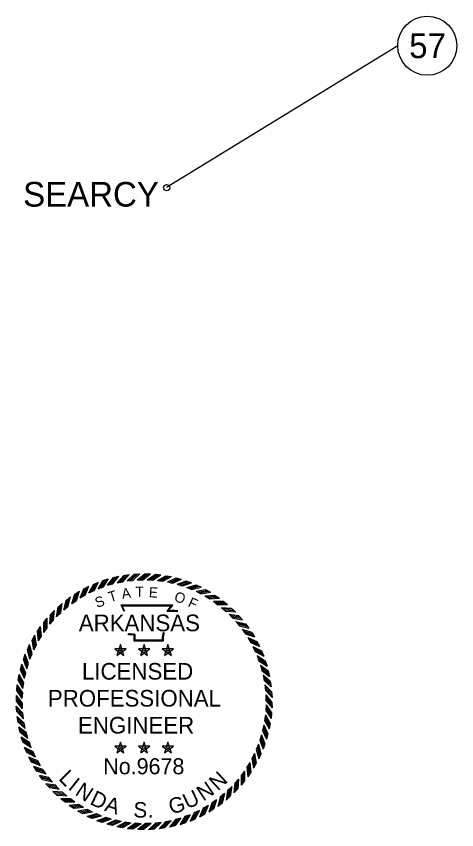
# Model space of a CAD drawing. Extents: x -13171 to 18763, y -8840 to 11152.
# Drawn here: x 13229 to 17512, y -8799 to -895 of the extents above; entities that cross this region are included whole.
import ezdxf

# ---------------------------------------------------------------- set-up
doc = ezdxf.new("R2010")
doc.units = 0
for name, color, linetype in [('Level 2', 7, 'Continuous'), ('Level 48', 7, 'Continuous'), ('Level 52', 7, 'Continuous')]:
    doc.layers.add(name, color=color, linetype=linetype)

msp = doc.modelspace()

# ---------------------------------------------------------------- linework, layer by layer
at = {"layer": 'Level 48'}
msp.add_line((16938.6, -1181.5), (14690.6, -2559.2), dxfattribs=at)
for centre, radius in [((17225.5, -1181.5), 286.9), ((14690.6, -2559.2), 30.2)]:
    msp.add_circle(centre, radius, dxfattribs=at)
at = {"layer": 'Level 52'}
for p, q in [((14274.6, -6328.5), (14328.3, -6319)), ((14376.6, -6316.3), (14430.9, -6311.3)), ((14479.8, -6313.2), (14534.3, -6313.2)), ((14581.9, -6317.3), (14636.2, -6321.3)), ((13979.6, -6414.7), (14029.2, -6392.3)), ((14075.4, -6377.8), (14126.8, -6359.7)), ((14174, -6349), (14226.7, -6335.2)), ((14211.5, -6398.5), (14265.3, -6389)), ((14307.9, -6380.8), (14362.3, -6375.8)), ((14405.4, -6371.2), (14460.1, -6371.2)), ((14503.4, -6369.7), (14557.9, -6373.7)), ((14601.2, -6376.3), (14655.2, -6384.8)), ((14683.7, -6330.6), (14737.5, -6339)), ((14698.2, -6390.9), (14751.2, -6403.8)), ((14784.1, -6352.1), (14837.1, -6365)), ((14882.4, -6382), (14934.1, -6399.2)), ((13798.6, -6511.4), (13843.9, -6481.2)), ((13887.1, -6459.3), (13934.7, -6432.9)), ((13935.5, -6498.1), (13985.3, -6475.7)), ((14024.7, -6457.3), (14076.1, -6439.1)), ((14116.8, -6424), (14169.7, -6410.1)), ((14793.5, -6413.5), (14845.4, -6430.7)), ((14886.7, -6443.8), (14936.9, -6465.3)), ((14977.9, -6419.8), (15028, -6441.2)), ((15069.9, -6465.4), (15118.1, -6490.8)), ((13714.7, -6570.7), (13757.3, -6536.8)), ((13850.1, -6546), (13897.8, -6519.6)), ((14977.1, -6481.8), (15025.4, -6507.4)), ((15064, -6527.1), (15110, -6556.6)), ((15157.9, -6518.4), (15203.8, -6547.8)), ((13636, -6636.7), (13675.7, -6599.4)), ((13692.4, -6662.3), (13735.2, -6628.4)), ((13768.8, -6600.9), (13814.3, -6570.6)), ((15146.9, -6579.4), (15190.3, -6612.6)), ((15225.2, -6638.4), (15265.7, -6675)), ((15241.2, -6578.5), (15284.5, -6611.6)), ((13563, -6708.9), (13599.5, -6668.5)), ((13621.4, -6729.8), (13661.2, -6692.5)), ((15298.3, -6703.7), (15335.7, -6743.5)), ((15319.2, -6645.3), (15359.6, -6681.8)), ((15391.5, -6718.3), (15428.7, -6758)), ((13496.2, -6787), (13529.2, -6743.7)), ((13556.1, -6803), (13592.7, -6762.4)), ((15365.8, -6774.7), (15399.7, -6817.5)), ((15457.4, -6797), (15491.3, -6839.7)), ((13436.1, -6870.2), (13465.5, -6824.4)), ((13497.1, -6881.2), (13530.3, -6837.8)), ((15427.2, -6851.1), (15457.5, -6896.6)), ((13383, -6958.2), (13408.5, -6910)), ((13444.8, -6964.1), (13474.3, -6918.1)), ((15482.1, -6932.4), (15508.5, -6980.1)), ((15516.7, -6880.9), (15546.9, -6926.2)), ((13337.5, -7050.2), (13358.9, -7000.1)), ((13399.5, -7051), (13425.1, -7002.8)), ((14241.7, -7000.7), (14207.6, -7105.3)), ((14275.7, -7105.2), (14241.8, -7000.6)), ((14472.8, -7000.7), (14438.7, -7105.3)), ((14506.8, -7105.2), (14472.9, -7000.6)), ((14703.9, -7000.7), (14669.8, -7105.3)), ((14737.9, -7105.2), (14704, -7000.6)), ((15530.1, -7017.8), (15552.5, -7067.6)), ((15568.8, -6969.4), (15595.2, -7017)), ((13299.6, -7145.7), (13316.9, -7094)), ((13361.5, -7141.4), (13383, -7091.2)), ((14296.6, -7040.6), (14186.7, -7040.5)), ((14186.7, -7040.6), (14275.7, -7105.4)), ((14207.7, -7105.2), (14296.8, -7040.7)), ((14233.9, -7058.2), (14250.2, -7058.2)), ((14241.8, -7052.3), (14241.8, -7066.1)), ((14527.8, -7040.6), (14417.8, -7040.5)), ((14417.9, -7040.6), (14506.8, -7105.4)), ((14438.8, -7105.2), (14527.9, -7040.7)), ((14465, -7058.2), (14481.3, -7058.2)), ((14472.9, -7052.3), (14472.9, -7066.1)), ((14758.9, -7040.6), (14648.9, -7040.5)), ((14649, -7040.6), (14737.9, -7105.4)), ((14670, -7105.2), (14759, -7040.7)), ((14696.1, -7058.2), (14712.4, -7058.2)), ((14704, -7052.3), (14704, -7066.1)), ((15570.9, -7107), (15589.1, -7158.4)), ((15613.5, -7061.9), (15635.8, -7111.5)), ((13269.8, -7244), (13282.7, -7191.1)), ((13331.2, -7234.6), (13348.4, -7182.8)), ((15650.3, -7157.7), (15668.5, -7209.1)), ((15604.1, -7199.2), (15618, -7252)), ((15679.1, -7256.3), (15693, -7309)), ((13248.2, -7344.4), (13256.7, -7290.6)), ((13308.6, -7330), (13321.5, -7276.9)), ((15629.7, -7293.8), (15639.1, -7347.6)), ((13235, -7446.3), (13239, -7391.9)), ((13294, -7426.9), (13302.5, -7372.9)), ((15647.3, -7390.2), (15652.3, -7444.6)), ((15699.7, -7356.9), (15709.1, -7410.6)), ((13230.3, -7548.9), (13229.8, -7494.4)), ((13287.4, -7524.7), (13291.4, -7470.2)), ((15656.9, -7487.7), (15657.4, -7542.4)), ((15711.9, -7458.9), (15716.9, -7513.2)), ((13288.9, -7622.7), (13288.4, -7568.1)), ((15658.4, -7585.7), (15654.4, -7640.2)), ((15715.6, -7561.6), (15716.1, -7616)), ((13234, -7651.5), (13229, -7597.3)), ((13298.5, -7720.2), (13293.5, -7665.9)), ((15710.8, -7664.2), (15706.8, -7718.5)), ((13246.2, -7753.5), (13236.7, -7699.8)), ((15651.9, -7683.5), (15643.4, -7737.5)), ((13266.7, -7854.1), (13252.9, -7801.4)), ((13316.2, -7816.7), (13306.7, -7762.9)), ((15637.2, -7780.5), (15624.3, -7833.5)), ((15697.6, -7766), (15689.1, -7819.8)), ((13295.5, -7952.7), (13277.4, -7901.3)), ((13341.7, -7911.3), (13327.8, -7858.5)), ((15614.7, -7875.8), (15597.4, -7927.7)), ((15676, -7866.4), (15663.1, -7919.4)), ((13375, -8003.5), (13356.8, -7952)), ((14241.7, -7948.3), (14207.6, -8052.9)), ((14275.7, -8052.8), (14241.8, -7948.2)), ((14472.8, -7948.3), (14438.7, -8052.9)), ((14506.8, -8052.8), (14472.9, -7948.2)), ((14703.9, -7948.3), (14669.8, -8052.9)), ((14737.9, -8052.8), (14704, -7948.2)), ((15584.3, -7969), (15562.8, -8019.2)), ((15646.2, -7964.7), (15629, -8016.4)), ((13332.4, -8048.6), (13310, -7998.9)), ((13415.7, -8092.6), (13393.3, -8042.8)), ((14296.6, -7988.2), (14186.7, -7988.1)), ((14186.7, -7988.2), (14275.7, -8053)), ((14207.7, -8052.8), (14296.8, -7988.3)), ((14233.9, -8005.8), (14250.2, -8005.8)), ((14241.8, -7999.9), (14241.8, -8013.7)), ((14527.8, -7988.2), (14417.8, -7988.1)), ((14417.9, -7988.2), (14506.8, -8053)), ((14438.8, -8052.8), (14527.9, -7988.3)), ((14465, -8005.8), (14481.3, -8005.8)), ((14472.9, -7999.9), (14472.9, -8013.7)), ((14758.9, -7988.2), (14648.9, -7988.1)), ((14649, -7988.2), (14737.9, -8053)), ((14670, -8052.8), (14759, -7988.3)), ((14696.1, -8005.8), (14712.4, -8005.8)), ((14704, -7999.9), (14704, -8013.7)), ((15546.3, -8059.4), (15520.8, -8107.7)), ((15608.4, -8060.2), (15586.9, -8110.3)), ((13377, -8141.1), (13350.6, -8093.4)), ((13463.7, -8178.1), (13437.3, -8130.3)), ((13429.1, -8229.6), (13398.9, -8184.2)), ((13518.6, -8259.3), (13488.3, -8213.9)), ((15501, -8146.3), (15471.6, -8192.3)), ((15562.8, -8152.2), (15537.3, -8200.4)), ((13488.4, -8313.5), (13454.5, -8270.8)), ((13580, -8335.7), (13546.1, -8292.9)), ((15448.7, -8229.2), (15415.6, -8272.6)), ((15509.8, -8240.2), (15480.4, -8286.1)), ((13554.4, -8392.2), (13517.1, -8352.4)), ((13647.5, -8406.8), (13610.2, -8366.9)), ((15389.7, -8307.5), (15353.1, -8348)), ((15449.7, -8323.5), (15416.6, -8366.8)), ((13626.6, -8465.2), (13586.2, -8428.6)), ((13720.7, -8472), (13680.1, -8435.4)), ((15253.4, -8448.1), (15210.6, -8482.1)), ((15324.5, -8380.6), (15284.6, -8418)), ((15382.9, -8401.5), (15346.3, -8441.9)), ((13704.7, -8532), (13661.4, -8498.9)), ((13798.9, -8531), (13755.5, -8497.9)), ((15177, -8509.5), (15131.5, -8539.8)), ((15309.9, -8473.8), (15270.1, -8511)), ((13787.9, -8592.1), (13742.1, -8562.7)), ((13881.8, -8583.3), (13835.8, -8553.9)), ((13968.7, -8628.6), (13920.5, -8603.1)), ((15010.3, -8612.4), (14960.5, -8634.8)), ((15095.8, -8564.4), (15048, -8590.8)), ((15147.3, -8599), (15101.9, -8629.2)), ((15231.2, -8539.7), (15188.5, -8573.6)), ((13875.9, -8645.1), (13827.7, -8619.6)), ((13967.9, -8690.7), (13917.8, -8669.2)), ((14059.1, -8666.6), (14008.9, -8645.1)), ((14152.3, -8697), (14100.5, -8679.7)), ((14829, -8686.4), (14776.2, -8700.3)), ((14921.2, -8653.2), (14869.7, -8671.4)), ((15058.8, -8651.1), (15011.1, -8677.5)), ((14063.4, -8728.5), (14011.7, -8711.3)), ((14161.7, -8758.3), (14108.8, -8745.4)), ((14247.7, -8719.6), (14194.6, -8706.6)), ((14262.1, -8779.9), (14208.3, -8771.4)), ((14344.6, -8734.2), (14290.6, -8725.7)), ((14442.4, -8740.7), (14387.9, -8736.7)), ((14540.4, -8739.2), (14485.8, -8739.7)), ((14637.9, -8729.6), (14583.6, -8734.6)), ((14734.3, -8712), (14680.6, -8721.4)), ((14771.8, -8761.4), (14719.1, -8775.3)), ((14870.4, -8732.6), (14819, -8750.8)), ((14966.3, -8695.8), (14916.6, -8718.1)), ((14364, -8793.1), (14309.6, -8789.1)), ((14466.6, -8797.9), (14412.1, -8798.4)), ((14569.2, -8794.2), (14515, -8799.2)), ((14671.2, -8782), (14617.5, -8791.4))]:
    msp.add_line(p, q, dxfattribs=at)
for points in [[(14247.3, -6392), (14310.4, -6321.9)], [(14265.2, -6389), (14328.3, -6319)], [(14307.8, -6380.9), (14376.5, -6316.3)], [(14325.3, -6379.4), (14394, -6314.9)], [(14344.1, -6377.3), (14412.8, -6312.7)], [(14362.2, -6375.8), (14430.9, -6311.2)], [(14405.4, -6371.3), (14479.7, -6313.3)], [(14422.9, -6371.4), (14497.3, -6313.5)], [(14441.8, -6371), (14516.2, -6313)], [(14460, -6371.2), (14534.3, -6313.2)], [(14503.4, -6369.7), (14581.8, -6317.4)], [(14520.9, -6371.2), (14599.2, -6318.8)], [(14539.8, -6372.2), (14618.2, -6319.8)], [(14557.8, -6373.7), (14636.2, -6321.3)], [(13968.6, -6482.9), (14012.7, -6399.6)], [(13985.3, -6475.6), (14029.3, -6392.3)], [(14024.6, -6457.4), (14075.4, -6377.9)], [(14041.2, -6451.7), (14092, -6372.2)], [(14058.9, -6445), (14109.7, -6365.5)], [(14076.1, -6439.1), (14126.8, -6359.6)], [(14116.8, -6424.1), (14173.9, -6349.1)], [(14133.8, -6419.8), (14190.9, -6344.8)], [(14152, -6414.6), (14209.1, -6339.6)], [(14169.6, -6410.1), (14226.7, -6335.1)], [(14211.4, -6398.5), (14274.6, -6328.5)], [(14228.7, -6395.7), (14291.9, -6325.6)], [(14601.2, -6376.3), (14683.6, -6330.6)], [(14618.5, -6379.2), (14700.9, -6333.5)], [(14637.2, -6381.7), (14719.7, -6336)], [(14655.1, -6384.7), (14737.6, -6339)], [(14698.1, -6390.9), (14784, -6352.2)], [(14715.1, -6395.2), (14801, -6356.5)], [(14733.6, -6399.3), (14819.5, -6360.5)], [(14751.2, -6403.8), (14837.1, -6365)], [(14793.5, -6413.5), (14882.3, -6382)], [(14810, -6419.2), (14898.9, -6387.7)], [(14828.1, -6424.8), (14917, -6393.3)], [(14845.3, -6430.7), (14934.2, -6399.1)], [(13814.2, -6570.6), (13843.9, -6481.2)], [(13850, -6546.1), (13887, -6459.4)], [(13865.4, -6537.8), (13902.4, -6451.1)], [(13881.8, -6528.2), (13918.8, -6441.5)], [(13897.8, -6519.6), (13934.8, -6432.9)], [(13935.5, -6498.1), (13979.5, -6414.8)], [(13951.5, -6491.1), (13995.6, -6407.7)], [(14886.6, -6443.9), (14977.8, -6419.8)], [(14902.7, -6450.9), (14993.9, -6426.8)], [(14920.3, -6458), (15011.4, -6433.9)], [(14936.9, -6465.3), (15028, -6441.2)], [(14977, -6481.8), (15069.8, -6465.4)], [(14992.4, -6490.2), (15085.3, -6473.7)], [(13706.3, -6651.6), (13728.5, -6560)], [(13720.8, -6639.5), (13743, -6547.9)], [(13735.2, -6628.4), (13757.4, -6536.8)], [(13768.8, -6601), (13798.5, -6511.5)], [(13783.5, -6591.4), (13813.2, -6501.9)], [(13799, -6580.6), (13828.7, -6491.1)], [(15009.4, -6498.7), (15102.2, -6482.2)], [(15025.3, -6507.3), (15118.1, -6490.8)], [(15063.9, -6527.1), (15157.8, -6518.4)], [(15078.6, -6536.7), (15172.5, -6528)], [(15094.8, -6546.6), (15188.6, -6537.8)], [(15110, -6556.5), (15203.8, -6547.7)], [(13621.4, -6729.9), (13635.9, -6636.8)], [(13634.3, -6718), (13648.8, -6624.9)], [(13647.8, -6704.8), (13662.4, -6611.6)], [(13661.1, -6692.5), (13675.7, -6599.3)], [(13692.4, -6662.4), (13714.6, -6570.8)], [(14276.8, -6677.9), (14247.8, -6615), (14750.3, -6614.7), (14708.3, -6667.5), (14742.4, -6667), (14770.9, -6666.7), (14799.4, -6669.8)], [(14284, -6674.6), (14260.2, -6623), (14733.7, -6622.7), (14691.6, -6675.6), (14742.5, -6675), (14770.6, -6674.6), (14798.6, -6677.7)], [(15146.8, -6579.4), (15241.1, -6578.5)], [(15160.6, -6590.2), (15254.9, -6589.2)], [(15175.9, -6601.4), (15270.2, -6600.4)], [(15190.3, -6612.5), (15284.5, -6611.6)], [(15225.1, -6638.4), (15319.1, -6645.2)], [(13556.1, -6803), (13562.9, -6709)], [(13568, -6790.1), (13574.8, -6696.1)], [(13580.4, -6775.8), (13587.2, -6681.8)], [(13592.7, -6762.5), (13599.5, -6668.4)], [(15238, -6650.3), (15332, -6657.1)], [(15252.3, -6662.7), (15346.3, -6669.5)], [(15265.7, -6675), (15359.7, -6681.8)], [(15298.2, -6703.7), (15391.4, -6718.2)], [(15310.1, -6716.6), (15403.2, -6731.1)], [(13497.1, -6881.3), (13496.2, -6787.1)], [(13507.9, -6867.5), (13506.9, -6773.2)], [(13519.1, -6852.2), (13518.1, -6757.9)], [(13530.2, -6837.9), (13529.2, -6743.6)], [(15323.4, -6730.1), (15416.5, -6744.7)], [(15335.7, -6743.4), (15428.8, -6758)], [(15365.7, -6774.7), (15457.4, -6796.9)], [(15376.5, -6788.6), (15468.1, -6810.8)], [(13444.8, -6964.2), (13436.1, -6870.3)], [(13454.4, -6949.5), (13445.7, -6855.7)], [(13464.3, -6933.4), (13455.5, -6839.5)], [(13474.2, -6918.2), (13465.4, -6824.3)], [(15388.6, -6803.1), (15480.2, -6825.3)], [(15399.7, -6817.5), (15491.4, -6839.7)], [(15427.1, -6851.1), (15516.6, -6880.8)], [(15436.7, -6865.8), (15526.2, -6895.5)], [(13407.9, -7035.7), (13391.4, -6942.9)], [(13416.4, -7018.8), (13399.9, -6925.9)], [(13425, -7002.8), (13408.5, -6910)], [(14671.1, -6888.5), (14662.5, -6895.5), (14659.7, -6905.9), (14656.8, -6931.9), (14656.8, -6966.7), (14376.3, -6966.7), (14376.3, -6919.8), (14376.3, -6909.4), (14364.9, -6905.9), (14325, -6905.9), (14317.9, -6895.1)], [(14666, -6882.3), (14655.5, -6890.9), (14651.8, -6904.4), (14648.9, -6931.5), (14648.9, -6958.7), (14384.3, -6958.7), (14384.3, -6919.8), (14384.3, -6903.5), (14366.1, -6897.9), (14329.3, -6897.9), (14324.6, -6890.7)], [(15447.6, -6881.3), (15537, -6911)], [(15457.5, -6896.5), (15547, -6926.2)], [(15482, -6932.3), (15568.7, -6969.3)], [(15490.4, -6947.7), (15577.1, -6984.7)], [(13368.6, -7125.4), (13344.5, -7034.3)], [(13375.7, -7107.9), (13351.6, -7016.7)], [(13383, -7091.2), (13358.9, -7000.1)], [(13399.5, -7051.1), (13383.1, -6958.3)], [(15499.9, -6964.1), (15586.6, -7001.1)], [(15508.5, -6980.1), (15595.2, -7017.1)], [(15530, -7017.8), (15613.4, -7061.8)], [(15537.1, -7033.8), (15620.4, -7077.9)], [(13342.5, -7200), (13310.9, -7111.1)], [(13348.4, -7182.8), (13316.8, -7094)], [(13361.6, -7141.5), (13337.5, -7050.3)], [(15545.2, -7050.9), (15628.6, -7095)], [(15552.5, -7067.6), (15635.9, -7111.6)], [(15570.8, -7106.9), (15650.2, -7157.7)], [(13321.4, -7277), (13282.7, -7191)], [(13331.2, -7234.7), (13299.7, -7145.8)], [(13336.9, -7218.1), (13305.4, -7129.2)], [(15576.5, -7123.5), (15655.9, -7174.3)], [(15583.2, -7141.2), (15662.6, -7192)], [(15589.1, -7158.4), (15668.5, -7209.1)], [(13308.6, -7330.1), (13269.9, -7244.1)], [(13312.9, -7313.1), (13274.2, -7227.1)], [(13317, -7294.6), (13278.2, -7208.6)], [(15604.1, -7199.1), (15679, -7256.2)], [(15608.4, -7216.1), (15683.3, -7273.3)], [(15613.6, -7234.3), (15688.6, -7291.4)], [(15618, -7251.9), (15693, -7309)], [(13294, -7427), (13248.3, -7344.5)], [(13296.9, -7409.7), (13251.2, -7327.2)], [(13299.4, -7390.9), (13253.7, -7308.5)], [(13302.4, -7373), (13256.7, -7290.6)], [(15629.6, -7293.7), (15699.6, -7356.9)], [(15632.5, -7311), (15702.5, -7374.2)], [(15636.2, -7329.6), (15706.2, -7392.7)], [(15639.2, -7347.5), (15709.2, -7410.6)], [(13288.9, -7507.3), (13236.5, -7428.9)], [(13289.9, -7488.4), (13237.5, -7410)], [(13291.4, -7470.3), (13239, -7391.9)], [(15647.2, -7390.1), (15711.8, -7458.8)], [(15648.7, -7407.6), (15713.2, -7476.3)], [(15650.8, -7426.4), (15715.4, -7495.1)], [(13288.4, -7568.2), (13229.7, -7494.3)], [(13287.4, -7524.8), (13235.1, -7446.4)], [(15652.3, -7444.5), (15716.9, -7513.2)], [(15656.9, -7487.7), (15715.5, -7561.5)], [(15656.9, -7505.2), (15715.5, -7579)], [(13288.4, -7586.3), (13229.7, -7512.5)], [(13289, -7605.2), (13230.3, -7531.4)], [(13289, -7622.8), (13230.3, -7549)], [(15657.5, -7524.1), (15716.1, -7597.9)], [(15657.5, -7542.3), (15716.1, -7616.1)], [(15658.4, -7585.7), (15710.8, -7664.1)], [(13293.5, -7665.9), (13228.9, -7597.2)], [(13295, -7684), (13230.4, -7615.3)], [(13297.1, -7702.8), (13232.6, -7634.1)], [(13298.6, -7720.3), (13234, -7651.6)], [(15654.5, -7640.2), (15706.8, -7718.5)], [(15656, -7622.1), (15708.3, -7700.5)], [(15656.9, -7603.2), (15709.3, -7681.6)], [(13306.7, -7762.9), (13236.7, -7699.8)], [(13309.6, -7780.8), (13239.6, -7717.7)], [(13313.3, -7799.4), (13243.3, -7736.3)], [(15643.4, -7737.4), (15689.1, -7819.9)], [(15646.4, -7719.5), (15692.1, -7802)], [(15648.9, -7700.8), (15694.7, -7783.2)], [(15651.8, -7683.5), (15697.5, -7765.9)], [(13316.2, -7816.7), (13246.2, -7753.6)], [(13327.8, -7858.5), (13252.8, -7801.4)], [(13332.3, -7876.1), (13257.3, -7819)], [(15628.8, -7815.9), (15667.6, -7901.8)], [(15632.9, -7797.4), (15671.7, -7883.3)], [(15637.2, -7780.4), (15676, -7866.3)], [(13337.5, -7894.3), (13262.5, -7837.2)], [(13341.8, -7911.3), (13266.8, -7854.2)], [(13356.8, -7952.1), (13277.3, -7901.3)], [(15608.9, -7892.4), (15640.5, -7981.2)], [(15614.6, -7875.8), (15646.2, -7964.6)], [(15624.4, -7833.5), (15663.1, -7919.4)], [(13362.6, -7969.2), (13283.2, -7918.5)], [(13369.4, -7986.9), (13289.9, -7936.2)], [(13375, -8003.5), (13295.6, -7952.8)], [(15584.3, -7969), (15608.3, -8060.1)], [(15597.5, -7927.6), (15629, -8016.5)], [(15603.4, -7910.4), (15634.9, -7999.3)], [(13393.3, -8042.9), (13310, -7998.9)], [(13400.6, -8059.5), (13317.3, -8015.5)], [(13408.8, -8076.6), (13325.4, -8032.6)], [(13415.8, -8092.7), (13332.5, -8048.6)], [(15546.3, -8059.3), (15562.8, -8152.1)], [(15562.9, -8019.2), (15587, -8110.4)], [(15570.2, -8002.6), (15594.2, -8093.7)], [(15577.2, -7985), (15601.3, -8076.2)], [(13437.3, -8130.4), (13350.6, -8093.4)], [(13445.9, -8146.3), (13359.2, -8109.3)], [(13455.5, -8162.7), (13368.7, -8125.7)], [(13463.8, -8178.1), (13377.1, -8141.1)], [(15520.8, -8107.6), (15537.3, -8200.5)], [(15529.5, -8091.7), (15545.9, -8184.5)], [(15538, -8074.7), (15554.4, -8167.6)], [(13488.3, -8213.9), (13398.9, -8184.2)], [(13498.3, -8229.1), (13408.8, -8199.4)], [(13509.1, -8244.6), (13419.6, -8214.9)], [(15471.6, -8192.3), (15480.4, -8286.1)], [(15481.6, -8177.1), (15490.3, -8271)], [(15491.4, -8160.9), (15500.2, -8254.8)], [(15501, -8146.2), (15509.8, -8240.1)], [(13518.7, -8259.3), (13429.2, -8229.6)], [(13546.1, -8293), (13454.5, -8270.8)], [(13557.2, -8307.3), (13465.6, -8285.1)], [(13569.3, -8321.9), (13477.7, -8299.7)], [(15415.6, -8272.6), (15416.6, -8366.8)], [(15426.8, -8258.3), (15427.7, -8352.5)], [(15437.9, -8243), (15438.9, -8337.2)], [(15448.7, -8229.1), (15449.7, -8323.4)], [(13580.1, -8335.7), (13488.5, -8313.5)], [(13610.2, -8367), (13517, -8352.4)], [(13622.5, -8380.4), (13529.3, -8365.8)], [(15353.2, -8348), (15346.3, -8442)], [(15365.5, -8334.6), (15358.6, -8428.6)], [(15377.8, -8320.3), (15371, -8414.3)], [(15389.7, -8307.4), (15382.9, -8401.4)], [(13635.7, -8393.9), (13542.6, -8379.3)], [(13647.6, -8406.8), (13554.5, -8392.2)], [(13680.2, -8435.5), (13586.1, -8428.6)], [(13693.5, -8447.8), (13599.5, -8440.9)], [(13707.8, -8460.1), (13613.8, -8453.3)], [(15253.4, -8448), (15231.2, -8539.7)], [(15284.7, -8418), (15270.1, -8511.1)], [(15298, -8405.7), (15283.5, -8498.8)], [(15311.6, -8392.4), (15297, -8485.6)], [(15324.5, -8380.5), (15309.9, -8473.7)], [(13720.7, -8472), (13626.7, -8465.2)], [(13755.6, -8497.9), (13661.3, -8498.9)], [(13769.9, -8509.1), (13675.6, -8510)], [(13785.2, -8520.2), (13690.9, -8521.2)], [(13799, -8531), (13704.7, -8532)], [(15146.8, -8529.9), (15117.1, -8619.4)], [(15162.3, -8519), (15132.6, -8608.5)], [(15177, -8509.4), (15147.3, -8598.9)], [(15210.7, -8482), (15188.5, -8573.7)], [(15225, -8470.9), (15202.8, -8562.5)], [(15239.6, -8458.8), (15217.4, -8550.4)], [(13835.9, -8553.9), (13742, -8562.7)], [(13851.1, -8563.9), (13757.2, -8572.6)], [(13867.2, -8573.7), (13773.3, -8582.5)], [(13881.9, -8583.3), (13788, -8592.1)], [(13920.5, -8603.1), (13827.7, -8619.6)], [(13936.5, -8611.8), (13843.6, -8628.2)], [(15010.4, -8612.3), (14966.3, -8695.7)], [(15048.1, -8590.8), (15011.1, -8677.6)], [(15064, -8582.2), (15027, -8668.9)], [(15080.4, -8572.7), (15043.4, -8659.4)], [(15095.8, -8564.3), (15058.8, -8651)], [(15131.6, -8539.8), (15101.9, -8629.3)], [(13953.4, -8620.3), (13860.6, -8636.7)], [(13968.8, -8628.6), (13876, -8645.1)], [(14008.9, -8645.2), (13917.8, -8669.3)], [(14025.6, -8652.5), (13934.4, -8676.5)], [(14043.1, -8659.5), (13952, -8683.6)], [(14059.2, -8666.6), (13968, -8690.7)], [(14100.5, -8679.8), (14011.7, -8711.3)], [(14117.7, -8685.7), (14028.8, -8717.2)], [(14135.8, -8691.3), (14046.9, -8722.8)], [(14812, -8690.7), (14754.9, -8765.6)], [(14829, -8686.4), (14771.9, -8761.3)], [(14869.8, -8671.4), (14819, -8750.8)], [(14886.9, -8665.5), (14836.2, -8744.9)], [(14904.6, -8658.8), (14853.9, -8738.2)], [(14921.2, -8653.1), (14870.5, -8732.5)], [(14960.6, -8634.8), (14916.6, -8718.2)], [(14977.2, -8627.5), (14933.2, -8710.9)], [(14994.3, -8619.4), (14950.3, -8702.7)], [(14152.4, -8696.9), (14063.5, -8728.5)], [(14194.7, -8706.7), (14108.7, -8745.4)], [(14212.3, -8711.1), (14126.3, -8749.9)], [(14230.7, -8715.2), (14144.8, -8754)], [(14247.7, -8719.5), (14161.8, -8758.3)], [(14290.7, -8725.7), (14208.2, -8771.4)], [(14308.6, -8728.7), (14226.2, -8774.4)], [(14327.4, -8731.2), (14244.9, -8777)], [(14344.7, -8734.1), (14262.2, -8779.8)], [(14388, -8736.8), (14309.6, -8789.1)], [(14406.1, -8738.3), (14327.7, -8790.6)], [(14425, -8739.3), (14346.6, -8791.6)], [(14442.5, -8740.7), (14364.1, -8793.1)], [(14485.8, -8739.8), (14412, -8798.4)], [(14504, -8739.8), (14430.2, -8798.4)], [(14522.9, -8739.2), (14449.1, -8797.8)], [(14540.5, -8739.2), (14466.7, -8797.8)], [(14583.6, -8734.6), (14514.9, -8799.2)], [(14601.7, -8733.1), (14533, -8797.7)], [(14620.5, -8731), (14551.8, -8795.5)], [(14638, -8729.5), (14569.3, -8794.1)], [(14680.6, -8721.5), (14617.5, -8791.5)], [(14698.5, -8718.5), (14635.4, -8788.5)], [(14717.1, -8714.8), (14654, -8784.8)], [(14734.4, -8711.9), (14671.3, -8781.9)], [(14776.2, -8700.3), (14719.1, -8775.3)], [(14793.8, -8695.9), (14736.7, -8770.9)]]:
    msp.add_lwpolyline(points, dxfattribs=at)

# ---------------------------------------------------------------- texts
at = {"layer": 'Level 2'}
msp.add_text('SEARCY', height=240, dxfattribs=at).set_placement((13295.9, -2744.3))
at = {"layer": 'Level 48'}
msp.add_text('57', height=240, dxfattribs=at).set_placement((17049.8, -1301.5))
at = {"layer": 'Level 52'}
for s, height, rotation, p in [('T', 99.1, 16.90148, (14141.1, -6588.4)), ('A', 99.1, 8.67877, (14261.5, -6556.9)), ('T', 99.1, 1.47887, (14389.5, -6537.2)), ('E', 99.1, 356.67203, (14516.3, -6540.2)), ('S', 99.1, 19.77256, (14015.1, -6644.9)), ('O', 99.1, 341.2218, (14757, -6574.2)), ('F', 99.1, 335.36282, (14890.6, -6626.5)), ('L', 150.5, 315.12954, (13633.3, -8308.4)), ('I', 150.5, 321.69595, (13724.8, -8399.5)), ('N', 150.5, 42.68166, (15189.2, -8427.4)), ('N', 150.5, 326.07356, (13791.4, -8454.2)), ('N', 150.5, 33.92644, (15048.3, -8526.2)), ('D', 150.5, 334.82877, (13936.1, -8547.5)), ('U', 150.5, 25.17123, (14893.9, -8602.4)), ('A', 150.5, 342.85438, (14079.8, -8612.8)), ('S', 150.5, 357.8112, (14365.9, -8678.6)), ('G', 150.5, 16.78082, (14736.7, -8652.6)), ('.', 150.5, 5.10721, (14509.3, -8683.2))]:
    msp.add_text(s, height=height, rotation=rotation, dxfattribs=at).set_placement(p)
for s, height, p in [('ARKANSAS', 161.78, (13837, -6870.4)), ('LICENSED', 161.78, (13867.8, -7340.6)), ('PROFESSIONAL', 161.779, (13536.5, -7602.6)), ('ENGINEER', 161.78, (13829.3, -7864.5)), ('No.9678', 156, (14075.1, -8260.5))]:
    msp.add_text(s, height=height, dxfattribs=at).set_placement(p)

doc.saveas('drawing.dxf')
